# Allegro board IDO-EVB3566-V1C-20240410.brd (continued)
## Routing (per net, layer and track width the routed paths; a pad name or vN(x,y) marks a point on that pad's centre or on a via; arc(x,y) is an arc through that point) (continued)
FE1.1_DM3: length 18.6
  TOP w0.114: U26.12 83.81,15.5 83.94,15.37 83.94,15.12 85.27,13.79 88.35,13.79 89.08,14.52 89.08,15.93 89.28,16.13 90.28,16.13 90.81,16.66 90.81,19.66 91.36,20.22 91.36,22.73 90.81,23.29 90.81,23.82 90.93,23.95 91.26,23.95 91.37,23.83 91.37,23.7 R151.1
FE1.1_DM3_: length 6.5
  TOP w0.114: R151.2 92.74,24.02 D32.10 D32.1 94.91,24.02 95.04,24.15 95.4,24.15 95.89,24.64 95.89,25.19 96.54,25.84 96.66,25.84 96.77,25.72 J37.2
FE1.1_DM4: length 13.6
  TOP w0.114: U26.15 86.36,16.79 86.49,16.92 86.75,16.92 86.96,17.13 88.88,17.13 90.04,18.29 90.04,19.91 90.42,20.29 90.42,22.61 90.04,22.99 90.04,24 90.68,24.64 90.68,25.47 90.93,25.72 91.26,25.72 91.37,25.61 91.37,25.48 R156.1
FE1.1_DM4_: length 22.7
  TOP w0.114: R156.2 92.5,25.55 93.26,25.55 D32.7 D32.4 94.61,25.52 94.74,25.65 95.12,25.65 95.76,26.29 95.76,27.09 96.37,27.7 97.69,27.7 98.18,27.21 98.18,24.16 99.71,22.63 99.71,16.66 101.2,15.17 102.12,15.17 102.23,15.06 J38.2
FE1.1_DP1: length 25.6
  TOP w0.114: R132.1 91.12,27.74 90.92,27.74 90.59,27.4 90.59,26.59 89.83,25.83 89.83,25.35 88.41,23.93 79.25,23.93 78.71,23.39 78.02,23.39 76.73,22.11 76.73,18.79 77.36,18.16 80.09,18.16 80.21,18.29 U26.4
FE1.1_DP1_: length 15.9
  TOP w0.114: J13.3 102.23,26.14 102.12,26.03 100.71,26.03 99.44,27.3 99.44,29.84 98.81,30.48 96.65,30.48 95.68,29.51 95.68,28.48 95.14,27.95 94.76,27.95 94.65,28.05 D31.2 D31.9 93.08,27.84 92.58,27.84 R132.2
FE1.1_DP2: length 29.6
  TOP w0.114: R149.1 91.06,29.58 90.66,29.58 90.48,29.41 90.48,28.34 90.37,28.23 90.36,28.23 89.88,27.74 89.88,26.95 89.17,26.24 89.17,25.65 88.05,24.53 78.88,24.53 78.46,24.11 77.82,24.11 76.16,22.45 76.16,17.72 77.03,16.85 80.07,16.85 80.14,16.79 U26.7
FE1.1_DP2_: length 12.1
  TOP w0.114: J36.3 96.77,36.89 96.66,36.77 96.08,36.77 95.52,36.21 95.52,30.65 95.04,30.17 95.04,29.56 94.92,29.45 94.76,29.45 94.66,29.55 D31.5 D31.6 93.19,29.45 92.87,29.45 R149.2
FE1.1_DP3: length 18.6
  TOP w0.114: U26.13 84.31,15.48 84.18,15.35 84.18,15.22 84.5,14.91 84.66,14.91 84.73,14.98 84.89,14.98 85.05,14.82 85.05,14.66 84.98,14.58 84.98,14.42 85.37,14.03 88.25,14.03 88.84,14.62 88.84,16.03 89.18,16.37 90.18,16.37 90.56,16.76 90.56,19.76 91.12,20.32 91.12,22.63 90.56,23.19 90.56,23.92 90.83,24.19 91.26,24.19 91.37,24.3 91.37,24.43 R154.1
FE1.1_DP3_: length 6.5
  TOP w0.114: J37.3 96.77,26.19 96.66,26.08 96.44,26.08 95.64,25.29 95.64,24.74 95.3,24.39 95.04,24.39 94.91,24.52 D32.2 D32.9 93.07,24.3 92.87,24.3 92.83,24.26 92.6,24.26 R154.2
FE1.1_DP4: length 13.6
  TOP w0.114: U26.16 86.36,17.29 86.49,17.16 86.65,17.16 86.86,17.37 88.78,17.37 89.8,18.39 89.8,20.01 90.18,20.39 90.18,22.51 89.8,22.89 89.8,24.1 90.44,24.74 90.44,25.57 90.83,25.97 91.26,25.97 91.37,26.08 91.37,26.21 R159.1
FE1.1_DP4_: length 22.7
  TOP w0.114: J38.3 102.23,15.53 102.12,15.41 101.3,15.41 99.95,16.76 99.95,22.73 98.42,24.26 98.42,27.3 97.79,27.94 96.27,27.94 95.52,27.19 95.52,26.39 95.02,25.89 94.76,25.89 94.63,26.02 D32.5 D32.6 93.2,25.93 92.7,25.93 R159.2
FE1_1_DM0: length 2
  TOP w0.114: R299.2 79.31,19.81 79.63,19.49 79.8,19.49 79.97,19.66 80.13,19.66 80.26,19.79 U26.1
FE1_1_XIN: length 6.1
  TOP w0.127: U26.10 82.81,13.65 C203.2 82.91,12.87 82.91,11.45 XT5.1
FE1_1_XOUT: length 4.6
  TOP w0.127: U26.11 83.31,13.86 83.52,13.65 C202.2 83.26,13.05 83.26,12.5 83.56,12.2 XT5.3
FE2_1_DP0: length 2
  TOP w0.114: R298.2 79.31,18.92 79.63,19.25 79.9,19.25 80.07,19.42 80.13,19.42 80.26,19.29 U26.2
GMAC1_MCLKINOUT_M0: length 8.1
  TOP w0.127: v1(24.77,20.06) M1.79
  BOTTOM w0.127: v1(24.77,20.06) 25.28,20.06 27.76,17.58 C383.2 R1224.1
GMAC1_MDC_M0: length 12.6
  TOP w0.127: v1(24.64,22.61) 24.09,22.06 M1.77
  BOTTOM w0.127: v1(24.64,22.61) 25.02,22.99 25.8,22.99 25.92,22.88 25.92,22.21 26.03,22.1 26.19,22.1 26.3,22.21 26.3,22.88 26.41,22.99 26.57,22.99 26.68,22.88 26.68,21.96 26.79,21.84 26.95,21.84 27.06,21.96 27.06,22.88 27.17,22.99 27.53,22.99 28.14,23.6 30.89,23.6 31.13,23.36 U11.22
GMAC1_MDIO_M0: length 12.3
  TOP w0.127: v1(24.77,23.75) 24.08,23.06 M1.76
  BOTTOM w0.127: U11.23 31.26,23.86 31.12,24 29.62,24 R1204.2 29.03,24.59 27.76,24.59 26.92,23.75 26.76,23.75 26.65,23.86 26.65,24.53 26.54,24.64 26.38,24.64 26.27,24.53 26.27,23.86 26.16,23.75 26,23.75 25.89,23.86 25.89,24.53 25.78,24.64 25.62,24.64 25.51,24.53 25.51,23.86 25.39,23.75 v1(24.77,23.75)
GMAC1_RSTN: length 9.4
  TOP w0.127: v1(25.25,21.69) 25.25,19.28 24.64,18.67 24.64,17.27 24.43,17.06 M1.82
  BOTTOM w0.127: R1201.1 26.09,21.34 25.73,21.69 v1(25.25,21.69)
GMAC1_RXD0_M0: length 24.3
  TOP w0.127: v1(34.84,16.34) 34.39,15.89 34.23,15.89 33.49,16.63 33.49,16.79 33.86,17.16 33.86,17.32 33.75,17.43 33.59,17.43 33.22,17.06 33.06,17.06 32.85,17.27 32.69,17.27 32.58,17.16 32.58,17.01 32.8,16.78 32.8,16.63 32.68,16.5 32.68,16.35 32.79,16.23 32.95,16.23 33.07,16.36 33.23,16.36 33.96,15.62 33.96,15.47 33.66,15.16 33.66,14.91 33.77,14.79 34.28,14.79 34.39,14.68 34.39,14.52 34.28,14.41 33.72,14.41 33.6,14.3 33.6,14.14 33.72,14.03 34.28,14.03 34.39,13.92 34.39,13.76 34.28,13.65 34.01,13.65 33.89,13.54 33.89,12.94 33.78,12.83 33.63,12.83 33.51,12.94 33.51,13.54 33.4,13.65 33.15,13.65 33.02,13.52 33.02,12.93 32.89,12.81 32.71,12.81 32.6,12.92 32.6,13.48 32.49,13.59 32.33,13.59 32.22,13.48 32.22,12.92 32.11,12.81 31.95,12.81 31.84,12.92 31.84,13.48 31.73,13.59 31.57,13.59 31.46,13.48 31.46,12.92 31.09,12.55 30.71,12.55 30.03,11.87 M1.92
  BOTTOM w0.127: R1206.2 37.85,17.4 36.96,16.51 35.01,16.51 v1(34.84,16.34)
GMAC1_RXD1_M0: length 23.1
  TOP w0.127: M1.93 31.03,11.98 31.6,12.55 38.21,12.55 38.35,12.7 38.35,13.08 38.23,13.21 37.39,13.21 37.26,13.34 37.26,14.96 37.14,15.09 36.96,15.09 36.83,14.96 36.83,13.21 36.7,13.08 36.51,13.08 36.4,13.19 36.4,13.48 36.29,13.59 36.13,13.59 36.02,13.48 36.02,13.19 35.91,13.08 35.66,13.08 35.54,13.19 35.54,13.56 35.43,13.67 35.28,13.67 35.16,13.56 35.16,13.19 35.05,13.08 34.8,13.08 34.64,13.24 34.64,15.49 35.56,16.41 36.01,16.41 v1(36.58,16.98)
  BOTTOM w0.127: v1(36.58,16.98) 36.58,17.1 36.96,17.48 R1205.2
GMAC1_RXDV_CRS_M0: length 25.7
  TOP w0.127: v1(30.56,27.11) 30.77,27.11 31.28,26.59 31.28,26.13 30.23,25.08 30.23,19.46 30.86,18.82 30.86,16.13 30.78,16.05 30.78,15.45 31.06,15.16 31.06,13.9 30.25,13.08 28.7,13.08 28.43,12.81 26.9,12.81 26.03,11.94 M1.88
  BOTTOM w0.127: v1(30.56,27.11) R1209.2 29.97,26.77 30.35,26.39 30.35,26.19 30.93,25.61 32.7,25.61 33.04,25.27 U11.26
GMAC1_RXER_M0: length 24.9
  TOP w0.127: M1.87 25.03,12.08 25.65,12.7 26.44,12.7 26.8,13.06 28.17,13.06 28.45,13.34 30.14,13.34 30.73,13.93 30.73,15.13 30.52,15.34 30.52,16.15 30.61,16.23 30.61,18.72 29.97,19.35 29.97,25.48 30.82,26.33 v1(30.82,26.4)
  BOTTOM w0.127: U11.28 34.04,25.27 33.76,25.55 33.12,25.55 32.8,25.87 32.48,25.87 R1212.1 31.21,27.11 30.82,26.71 v1(30.82,26.4)
GMAC1_TXD0_M0: length 14.5
  TOP w0.127: M1.86 24.11,13.06 24.94,13.89 24.94,15.93 25.45,16.43 25.45,18.36 25.78,18.69 27.39,18.69 27.67,18.41 27.8,18.41 v1(27.82,18.39)
  BOTTOM w0.127: v1(27.82,18.39) 27.82,18.42 29,19.6 30.45,19.6 31.05,20.21 U11.16
GMAC1_TXD1_M0: length 13.2
  TOP w0.127: M1.85 24.09,14.06 24.61,14.58 24.61,16.21 25.1,16.69 25.1,18.47 25.69,19.06 v1(27.68,19.06)
  BOTTOM w0.127: U11.17 31.34,20.85 30.34,19.85 28.63,19.85 27.82,19.05 27.69,19.05 27.69,19.06 v1(27.68,19.06)
GMAC1_TXEN_M0: length 12.6
  TOP w0.127: M1.78 v1(24.77,21.06)
  BOTTOM w0.127: U11.20 31.37,22.36 29.84,20.83 27.36,20.83 27.25,20.72 27.25,19.92 27.14,19.81 26.98,19.81 26.87,19.92 26.87,20.72 26.76,20.83 26.6,20.83 26.49,20.72 26.49,19.92 26.38,19.81 26.22,19.81 26.11,19.92 26.11,20.72 25.99,20.83 25,20.83 v1(24.77,21.06)
GPIO0_A5_USB_OTG_PWREN: length 61.5
  TOP w0.127: U13.4 75.39,55.07 74.8,54.48 v1(71.85,54.48) ; v1(69.98,25.37) 70.48,24.87 M1.215 ; v1(66.77,50.27) 65.79,49.29 65.79,46.43 65.77,46.41 65.77,45.5 65.79,45.49 65.79,37.08 63.63,34.92 62.61,34.92 v1(61.85,34.16)
  BOTTOM w0.127: v1(61.85,34.16) 62.1,34.41 68.74,34.41 69.72,33.43 69.72,31.52 69.98,31.26 v1(69.98,25.37) ; v1(66.77,50.27) 67.08,49.95 67.62,49.95 68.07,50.4 68.07,51.82 70.23,53.98 71.34,53.98 v1(71.85,54.48) 73.15,55.78 74.24,55.78 74.58,56.12 74.58,56.68 74.89,56.98 74.89,59.07 74.02,59.94 R117.2
GPIO0_A6_USB_OTG0_DET: length 48.7
  TOP w0.127: v1(66.1,50.36) 65.53,49.8 65.53,46.53 65.52,46.52 65.52,45.4 65.53,45.38 65.53,37.19 63.65,35.31 62.23,35.31 v1(61.85,34.92) ; v1(65.28,55.3) 65,55.02 60.54,55.02 v1(60.38,55.18) ; M1.216 70.48,26.11 71.2,25.4 v1(71.53,25.4)
  BOTTOM w0.127: R120.1 v1(60.38,55.18) ; v1(61.85,34.92) 62.04,34.73 68.78,34.73 69.98,33.54 69.98,31.62 71.53,30.07 v1(71.53,25.4) ; v1(66.1,50.36) 66.1,54.81 65.61,55.3 v1(65.28,55.3)
GPIO0_B0_U_TP_INT_L: length 38
  TOP w0.127: v1(68.73,13.27) 66.13,13.27 65.89,13.51 65.89,13.69 65.56,14.02 65.56,14.32 65.51,14.37 65.51,14.55 65.45,14.61 65.45,15.16 65.51,15.22 65.51,15.36 64.47,16.39 64.47,17.63 64.16,17.95 64.16,34.44 67.69,37.97 71.41,37.97 72.5,39.06 M1.161
  BOTTOM w0.127: v1(68.73,13.27) 68.07,12.62 R44.1
GPIO0_C7_D_TP_RST_L: length 28.8
  TOP w0.127: M1.154 73.03,32.06 71.58,30.61 69.62,30.61 69.37,30.35 69.37,29.37 68.42,28.42 66.27,28.42 65.53,27.68 65.53,18.37 65.74,18.16 65.74,17.58 66.28,17.04 66.28,16.68 66.79,16.18 67.72,16.18 68.6,15.3 68.6,14.74 68.61,14.73 68.61,14.26 v1(68.66,14.2)
  BOTTOM w0.127: v1(68.66,14.2) 68.67,14.2 69.34,13.53 69.34,12.78 69.09,12.53 R43.1
GPIO0_D3_CIF_PDN_L: length 43.1
  TOP w0.127: M1.217 69.97,29.61 68.52,28.16 66.38,28.16 65.79,27.57 65.79,18.48 66,18.27 66,17.69 66.54,17.15 66.54,16.79 66.89,16.43 67.61,16.43 67.82,16.43 68.85,15.4 68.85,14.84 69.27,14.42 v1(69.3,14.42)
  BOTTOM w0.127: v1(69.3,14.42) 69.6,14.13 69.6,10.16 68.83,9.4 68.83,7.49 68.07,6.73 65.41,6.73 64.5,5.83 55.38,5.83 55.17,6.04 J10.6
GPIO2_B1_WIFI_REG_ON_H: length 72.7
  TOP w0.127: v1(30.95,40.11) 30.95,40.11 30.61,40.45 28.39,40.45 27.61,41.22 25.72,41.22 25.54,41.41 25.54,43.61 25.03,44.12 25.03,45.29 24.77,45.56 24.77,46.35 24.06,47.06 M1.52 ; v1(79.63,47.41) 79.63,46.23 80.34,45.52 U10.12
  BOTTOM w0.127: v1(79.63,47.41) 77.91,47.41 77.71,47.21 73.63,47.21 73.49,47.35 71.73,47.35 69.69,49.39 46.46,49.39 45.54,48.47 42.55,48.47 42.03,47.96 39.45,47.96 38.98,47.48 38.98,47.1 38.19,46.3 37.34,46.3 36.26,47.38 33.79,47.38 30.95,44.54 v1(30.95,40.11)
GPIO2_B2_WIFI_WAKE_HOST_H: length 74.7
  TOP w0.127: U10.13 80.22,44.62 78.99,45.85 v1(78.99,46.76) ; v1(30.93,39.06) 30.93,38.8 29.97,37.85 29.17,37.85 28.35,38.67 28.35,40.13 27.58,40.89 25.69,40.89 25.29,41.3 25.29,43.5 24.78,44.01 24.78,45.19 23.9,46.06 M1.53
  BOTTOM w0.127: v1(78.99,46.76) 78.62,46.39 78.32,46.39 78.29,46.35 78.11,46.35 78.08,46.32 73.26,46.32 73.2,46.39 70.99,46.39 68.91,48.46 45.89,48.46 45.64,48.22 42.65,48.22 42.14,47.7 39.73,47.7 39.24,47.21 39.24,46.99 38.29,46.05 37.23,46.05 36.15,47.13 33.9,47.13 31.42,44.65 31.42,39.55 v1(30.93,39.06)
GPIO2_B7_BT_REG_ON_H: length 57.1
  TOP w0.127: U10.34 v1(93.22,36.52) ; M1.225 42.89,45.51 v1(42.93,45.55)
  BOTTOM w0.127: v1(93.22,36.52) 87.62,36.52 79.54,44.61 79.06,44.61 78.05,43.6 70.23,43.6 69.97,43.87 69.76,43.87 69.64,43.99 68.15,43.99 67.99,44.15 58.85,44.15 58.5,44.5 51,44.5 50.03,45.47 43,45.47 v1(42.93,45.55)
GPIO2_C0_BT_WAKE_HOST_H: length 47
  TOP w0.127: M1.182 42.26,47.84 42.78,47.84 v1(42.86,47.75) ; v1(85.09,47.88) 85.71,47.25 U10.7
  BOTTOM w0.127: v1(85.09,47.88) 82.69,47.88 80.95,46.13 78.43,46.13 78.39,46.1 78.22,46.1 78.18,46.07 73.16,46.07 73.09,46.13 70.88,46.13 68.88,48.13 68.46,48.13 68.46,48.13 45.92,48.13 45.75,47.96 43.23,47.96 43.02,47.75 v1(42.86,47.75)
GPIO2_C1_HOST_WAKE_BT_H: length 52.5
  TOP w0.127: M1.226 38.58,46.58 39.23,47.24 v1(39.92,47.24) ; U10.6 86.61,47.52 86.25,47.88 v1(85.77,47.88)
  BOTTOM w0.127: v1(39.92,47.24) 39.97,47.29 43.75,47.29 44.04,47 45.35,47 46.23,47.88 68.56,47.88 68.77,47.88 70.77,45.88 72.99,45.88 73.05,45.81 78.29,45.81 78.32,45.85 78.5,45.85 78.53,45.88 80.57,45.88 81.05,45.88 82.54,47.37 85.26,47.37 v1(85.77,47.88)
GPIO2_C6_CIF_RST_L: length 126.2
  TOP w0.127: v1(54.67,7.7) 51.36,7.7 51.18,7.87 51.18,8.76 50.88,9.07 48.18,9.07 47.57,8.46 v1(45.49,8.46) ; v1(3.96,14.1) 3.96,12.06 9.93,6.1 12.32,6.1 v1(12.83,5.59) ; v1(3.96,18.87) 3.96,20.02 3.66,20.32 3.66,37.47 3.84,37.64 3.84,39.25 4.75,40.16 4.75,49.83 5.59,50.67 8.2,50.67 11.38,53.85 19.3,53.85 20.7,52.45 29.91,52.45 30.03,52.32 M1.43
  BOTTOM w0.127: v1(54.67,7.7) J10.5 ; v1(3.96,14.1) v1(3.96,18.87) ; v1(12.83,5.59) 13.31,6.07 16.79,6.07 17.27,5.59 23.62,5.59 24.13,6.1 31.24,6.1 31.54,5.8 36.93,5.8 37.34,6.21 40.34,6.21 44.06,9.93 45.16,9.93 45.29,9.8 45.29,8.66 v1(45.49,8.46)
GPIO3_D6_SPK_CTRL_L: length 77
  TOP w0.127: U25.1 81.62,27.77 82.08,28.23 82.08,30.95 81.95,31.07 U24.1 80.27,31.07 ; M1.75 24.06,24.06 25,25 25,27.28 25.23,27.52 25.23,30.31 24.78,30.77 24.78,32.63 v1(25.02,32.87) ; 80.27,31.07 80.25,31.07 79.32,32 77.82,32 77.29,31.48 v1(77.29,31.26) ; 80.27,31.07 R199.2
  BOTTOM w0.127: v1(25.02,32.87) 25.19,33.04 29.82,33.04 30.07,33.29 31.23,33.29 33.99,36.06 45.78,36.06 46.51,36.78 52.09,36.78 53.45,35.43 59.69,35.43 61.3,37.04 63.78,37.04 64.13,36.69 69.76,36.69 73.05,33.4 73.13,33.4 75.17,31.36 77.19,31.36 v1(77.29,31.26)
GPIO3_D7_LVDS_ON: length 83.8
  TOP w0.127: J7.36 74.55,10.23 75.18,10.87 v1(75.18,12.32) ; M1.74 23.2,25.06 22.81,24.67 22.81,23.06 22.27,22.52 22.27,10.66 22.86,10.07 22.86,7.74 v1(22.81,7.69)
  BOTTOM w0.127: v1(75.18,12.32) 75.18,12.38 74.76,12.81 74.76,13.32 72.61,15.47 71.95,15.47 71.27,16.15 71.27,16.55 70.68,17.14 65.09,17.14 64.41,16.47 63.6,16.47 63.18,16.89 50.72,16.89 48.79,14.96 46.63,14.96 46.06,14.39 45.54,14.39 39.68,8.53 36.55,8.53 35.88,7.85 32.98,7.85 32.58,8.26 28.38,8.26 27.98,7.85 22.97,7.85 v1(22.81,7.69)
GPIO4_A0_MIPI_TX1_RST_L: length 32.8
  TOP w0.127: v1(33.02,9.02) 33.02,8.31 R342.1 ; M1.72 22.84,26.37 22.84,25.6 22.56,25.31 22.56,23.17 22.01,22.63 22.01,8.42 v1(21.78,8.19)
  BOTTOM w0.127: v1(33.02,9.02) 32.74,9.3 28.71,9.3 27.77,8.36 23.15,8.36 22.85,8.65 22.24,8.65 v1(21.78,8.19)
GPIO4_B0_USB_HOST1_PWREN_H: length 77.4
  TOP w0.127: v1(59.45,35.9) 59.69,36.13 59.69,50.35 v1(59.54,50.51) ; v1(30.4,34.01) 30.62,34.22 30.62,34.97 27.56,38.02 25.47,38.02 24.78,38.72 24.78,40.37 24.09,41.06 M1.58
  BOTTOM w0.127: v1(59.54,50.51) 60.56,50.51 60.73,50.67 62.12,50.67 63.88,52.43 63.88,54.61 64.35,55.08 64.35,58.71 60.71,62.36 59.56,62.36 58.87,63.05 U14.4 ; v1(59.45,35.9) 59.24,35.69 53.55,35.69 52.2,37.04 50,37.04 49.32,37.72 44.32,37.72 43.17,36.56 33.75,36.56 31.2,34.01 v1(30.4,34.01)
GPIO4_B1_CIF_PWREN_H: length 93.3
  TOP w0.127: v1(21.12,8) 21.12,8.7 21.76,9.34 21.76,22.73 22.3,23.27 22.3,25.41 22.59,25.7 22.59,26.48 22.84,26.73 22.84,28.93 22.97,29.06 M1.70
  BOTTOM w0.127: R1221.1 77.12,8.23 77.37,8.23 77.85,8.71 77.85,9.96 78.74,10.85 78.74,12.31 77.71,13.34 75.11,13.34 72.72,15.72 72.05,15.72 71.52,16.25 71.52,16.66 70.78,17.4 64.98,17.4 64.31,16.72 63.71,16.72 63.29,17.14 50.62,17.14 48.68,15.21 46.52,15.21 45.95,14.64 45.44,14.64 39.58,8.78 36.45,8.78 35.77,8.1 33.09,8.1 32.43,8.76 28.53,8.76 27.87,8.1 23.05,8.1 23,8.15 22.42,8.15 21.99,7.72 21.4,7.72 v1(21.12,8)
GPIO4_B4_USB_FE_D4_PWREN_H: length 100.7
  TOP w0.127: M1.68 23.06,31.06 22.59,30.59 22.59,26.84 22.33,26.58 22.33,25.81 22.05,25.52 22.05,23.38 21.51,22.84 21.51,9.44 20.45,8.38 v1(20.45,7.95)
  BOTTOM w0.127: U19.4 86.8,12.13 86.49,12.45 86.49,13.54 85.33,14.7 78.87,14.7 75.91,17.65 64.88,17.65 64.2,16.98 63.82,16.98 63.39,17.4 50.51,17.4 48.61,15.49 46.45,15.49 45.85,14.89 45.33,14.89 39.47,9.03 34.87,9.03 34.35,9.55 28.6,9.55 27.66,8.61 23.25,8.61 22.96,8.91 21.09,8.91 20.45,8.26 v1(20.45,7.95)
GPIO4_B5_HUB_XRSTJ: length 96.5
  TOP w0.127: v1(89.53,20.57) 89.53,18.82 88.62,17.91 R343.2 ; M1.67 24.06,32.06 24.52,32.52 24.52,33.03 25.65,34.16 27.49,34.16 27.57,34.08 28.28,34.08 28.49,33.87 28.49,29.88 v1(28.28,29.67) ; v1(48.51,33.99) 47.96,33.44 47.96,32.01 47.75,31.8 47.75,25.71 47.94,25.52 47.94,24.92 47.65,24.64 47.65,23.46 46.84,22.65 46.84,22.64 46.84,22.63 46.74,22.53 46.74,21.37 v1(46.96,21.15)
  BOTTOM w0.127: v1(89.53,20.57) 89.51,20.6 88.32,20.6 87.51,21.41 86.14,21.41 84.69,22.85 80.29,22.85 79.75,23.39 76.1,23.39 72.39,19.68 69.58,19.68 69.08,19.19 67.98,19.19 67.51,19.66 64.57,19.66 64.1,19.19 48.94,19.19 47.09,21.03 47.07,21.03 v1(46.96,21.15) ; v1(28.28,29.67) 28.33,29.72 30.48,29.72 30.73,29.97 31.78,29.97 31.78,29.97 31.9,29.97 35.24,33.31 47.84,33.31 v1(48.51,33.99)
GPIO4_B6_USB_FE_D2_PWREN_H: length 75.8
  TOP w0.127: v1(30.06,34.59) 30.06,34.6 30.06,35.16 27.45,37.77 25.37,37.77 24.52,38.62 24.52,39.61 24.07,40.06 M1.59
  BOTTOM w0.127: U17.4 88.84,30.8 89.28,31.24 89.28,32.98 89.07,33.19 86.76,33.19 85.95,32.38 82.47,32.38 81.2,33.66 73.15,33.66 69.87,36.94 64.28,36.94 63.93,37.29 50.11,37.29 49.43,37.97 44.2,37.97 43.04,36.82 33.64,36.82 31.42,34.59 v1(30.06,34.59)
GPIO4_B7_USB_FE_D3_PWREN_H: length 91.8
  TOP w0.127: M1.64 24.65,35.06 24.89,35.31 27.43,35.31 27.89,34.84 28.7,34.84 29.25,34.29 29.25,29.91 v1(29.97,29.19) ; v1(49.19,34.07) 49.15,34.03 49.15,33.96 48.71,33.52 48.63,33.52 48.22,33.1 48.22,31.91 48.01,31.7 48.01,25.81 48.19,25.63 48.19,24.82 47.9,24.53 47.9,23.34 47.38,22.82 47.37,22.82 47.09,22.55 47.09,22.53 47.09,22.53 47.09,21.89 v1(47.21,21.77)
  BOTTOM w0.127: U18.4 87.82,22.04 87.53,21.74 86.23,21.74 84.87,23.11 80.45,23.11 79.91,23.65 75.97,23.65 72.26,19.94 69.47,19.94 69.45,19.91 68.97,19.44 68.09,19.44 67.61,19.91 64.47,19.91 63.99,19.44 49.22,19.44 47.42,21.23 47.42,21.34 47.21,21.55 v1(47.21,21.77) ; v1(49.19,34.07) 49.15,34.03 49.15,33.96 48.71,33.52 48.68,33.52 48.22,33.06 35.36,33.06 32.02,29.72 31.89,29.72 31.89,29.72 30.87,29.72 30.35,29.19 v1(29.97,29.19)
GPIO4_C0_USB_HOST2_PWREN_H: length 96.9
  TOP w0.127: v1(47.56,22.36) 47.56,22.44 48.16,23.04 48.16,24.43 48.45,24.71 48.45,25.73 48.26,25.92 48.26,31.59 48.47,31.8 48.47,32.94 48.79,33.27 48.81,33.27 49.1,33.55 49.35,33.55 49.74,33.94 49.74,36.64 49.13,37.25 v1(49.03,37.25) ; v1(29.72,33.6) 29.59,33.73 29.59,35.27 27.35,37.52 25.26,37.52 25.24,37.54 23.72,39.06 M1.60
  BOTTOM w0.127: v1(29.72,33.6) 29.9,33.6 29.95,33.55 31.12,33.55 33.88,36.31 45.68,36.31 46.7,37.34 48.94,37.34 v1(49.03,37.25) ; v1(47.56,22.36) 47.56,22.35 47.56,22.08 47.68,21.97 47.68,21.48 49.46,19.69 63.89,19.69 64.36,20.17 67.72,20.17 68.19,19.69 68.87,19.69 69.37,20.19 72.16,20.19 75.87,23.9 80.11,23.9 80.65,23.36 85.12,23.36 86.39,22.1 87,22.1 87.96,23.06 89.15,23.06 89.25,23.16 89.25,25.76 88.9,26.1 U27.4
GPIO4_C1_USB_FE_D1_PWREN_H: length 95.9
  TOP w0.127: v1(47.5,32.21) 47.5,25.6 47.68,25.42 47.68,25.03 47.4,24.74 47.4,23.57 46.43,22.61 46.43,20.93 v1(46.89,20.47) ; v1(28.07,28.69) 28.74,29.36 28.74,34.08 28.49,34.33 27.68,34.33 27.47,34.54 25.53,34.54 24.05,33.06 M1.66
  BOTTOM w0.127: v1(46.89,20.47) 48.43,18.93 64.2,18.93 64.68,19.4 67.34,19.4 67.81,18.93 69.18,18.93 69.68,19.43 72.64,19.43 76.35,23.14 79.6,23.14 80.19,22.56 84.53,22.56 86,21.08 87.4,21.08 88.21,20.27 89.14,20.27 89.36,20.05 89.36,17.41 89.03,17.08 U15.4 ; v1(47.5,32.21) 47.15,32.55 35.57,32.55 32.23,29.21 32.1,29.21 32.1,29.21 31.08,29.21 30.35,28.47 28.28,28.47 v1(28.07,28.69)
HDMI_TX_CEC_PORT: length 7.4
  TOP w0.127: Q1.3 84.22,53.98 84.07,54.12 84.07,54.48 84.48,54.89 D9.1 83.98,56.92 J6.13
HDMI_TX_CLKN: length 48.3
  TOP w0.102: M1.139 73.91,17.43 74.17,17.43 75.74,19.01 75.74,22.5 76.76,23.52 76.76,43.94 76.76,43.95 76.76,44.53 76.76,44.54 76.76,46.96 78.72,48.92 78.72,52.18 81.59,55.05 82.46,55.05 83.1,55.68 83.1,56.12 83.22,56.24 D7.5 D7.6 83.22,57.55 83.1,57.67 83.1,58.79 83.48,59.17 J6.12
HDMI_TX_CLKP: length 48.3
  TOP w0.102: J6.10 82.48,59.17 82.84,58.81 82.84,57.7 82.72,57.57 D7.7 D7.4 82.72,56.22 82.84,56.1 82.84,55.79 82.36,55.3 81.48,55.3 78.47,52.28 78.47,49.03 76.5,47.07 76.5,44.64 76.5,44.64 76.5,43.84 76.5,43.84 76.5,23.63 75.49,22.61 75.49,19.12 75.11,18.74 74.97,18.74 74.86,18.84 74.72,18.84 74.58,18.7 74.58,18.55 74.68,18.45 74.68,18.31 74.06,17.69 73.91,17.69 M1.140
HDMI_TX_D0N: length 47.8
  TOP w0.102: J6.9 81.98,59.17 81.6,58.79 81.6,57.72 81.72,57.6 D7.9 D7.2 81.72,56.22 81.57,56.07 81.57,55.88 81.32,55.63 81.03,55.63 77.98,52.58 77.98,48.9 77.57,48.48 77.21,48.48 76.56,49.13 76.42,49.13 76.13,48.85 76.13,48.7 76.78,48.05 76.78,47.7 76.1,47.02 76.1,23.7 75.13,22.73 75.13,19.75 74.81,19.44 73.92,19.44 73.54,19.06 M1.141
HDMI_TX_D0P: length 47.8
  TOP w0.102: J6.7 80.98,59.17 81.34,58.81 81.34,57.72 81.22,57.6 D7.10 D7.1 81.22,56.22 81.32,56.12 81.32,55.98 81.22,55.88 80.92,55.88 77.72,52.68 77.72,49 77.46,48.74 77.32,48.74 76.67,49.39 76.31,49.39 75.88,48.95 75.88,48.6 76.53,47.95 76.53,47.8 75.84,47.12 75.84,23.8 74.87,22.83 74.87,20.82 74.77,20.72 74.65,20.72 74.55,20.62 74.55,20.42 74.65,20.32 74.77,20.32 74.87,20.21 74.87,19.86 74.7,19.69 73.91,19.69 M1.142
HDMI_TX_D1N: length 46.3
  TOP w0.102: J6.6 80.48,59.17 80.1,58.8 80.1,57.7 80.22,57.57 D6.6 D6.5 80.22,56.22 80.1,56.1 80.1,55.84 77.22,52.96 77.22,52.07 76.97,51.82 75.54,51.82 75.44,51.71 75.44,51.28 75.54,51.18 76.83,51.18 77.09,50.93 77.09,50.29 76.84,50.04 75.49,50.04 75.39,49.94 75.39,23.8 74.46,22.88 74.46,21.76 74.14,21.44 73.91,21.44 M1.143
HDMI_TX_D1P: length 46.2
  TOP w0.102: M1.144 73.91,21.69 74.03,21.69 74.21,21.87 74.21,22.98 75.13,23.91 75.13,50.04 75.38,50.29 76.73,50.29 76.83,50.39 76.83,50.82 76.73,50.93 75.43,50.93 75.18,51.18 75.18,51.82 75.43,52.07 76.86,52.07 76.96,52.17 76.96,53.06 79.15,55.25 79.15,55.4 79.07,55.48 79.07,55.62 79.21,55.77 79.35,55.77 79.44,55.68 79.58,55.68 79.85,55.95 79.85,56.04 79.72,56.17 D6.4 D6.7 79.72,57.62 79.85,57.75 79.85,58.81 79.48,59.17 J6.4
HDMI_TX_D2N: length 47
  TOP w0.102: M1.145 73.91,23.44 74.24,23.44 74.73,23.93 74.73,52.38 74.16,52.94 72.76,52.94 72.66,53.05 72.66,53.51 72.76,53.61 74.59,53.61 75.38,52.82 75.73,52.82 76.17,53.25 76.17,53.61 75.68,54.09 75.68,54.24 75.97,54.53 76.11,54.53 76.6,54.04 76.95,54.04 78.6,55.69 78.6,56.12 78.72,56.24 D6.2 D6.9 78.72,57.55 78.6,57.67 78.6,58.87 78.98,59.25 J6.3
HDMI_TX_D2P: length 47
  TOP w0.102: J6.1 77.98,59.25 78.35,58.88 78.35,57.67 78.22,57.55 D6.10 D6.1 78.22,56.27 78.35,56.15 78.35,55.79 78.12,55.57 77.97,55.57 77.89,55.65 77.75,55.65 77.6,55.51 77.6,55.36 77.69,55.28 77.69,55.14 76.85,54.29 76.7,54.29 76.22,54.78 75.86,54.78 75.43,54.34 75.43,53.99 75.91,53.5 75.91,53.36 75.62,53.07 75.48,53.07 74.69,53.86 72.66,53.86 72.41,53.61 72.41,52.94 72.66,52.69 74.06,52.69 74.47,52.27 74.47,24.03 74.13,23.69 73.91,23.69 M1.146
HDMI_TX_HPD_PORT: length 7.4
  TOP w0.127: J6.19 86.98,58.91 v1(86.61,58.55)
  BOTTOM w0.127: R30.2 R28.2 87.12,56.26 87.33,56.47 87.33,57.34 87.02,57.66 86.33,57.66 D8.1 86.23,58.17 v1(86.61,58.55)
HDMI_TX_HPDIN: length 80.9
  TOP w0.127: M1.135 73.9,13.06 74.3,13.46 76.17,13.46 v1(76.51,13.8)
  BOTTOM w0.127: v1(76.51,13.8) 77.61,13.8 78.99,12.41 78.99,10.39 79.96,9.42 97.94,9.42 99.92,11.4 99.92,16.36 100.81,17.25 100.81,31.39 99.92,32.28 99.92,39.57 95.43,44.07 93.27,44.07 91.69,45.65 91.69,46.61 88.77,49.53 88.77,50.75 87.12,52.4 R28.1
HDMI_TXDDC_SCL_PORT: length 8.9
  TOP w0.127: J6.15 84.98,58.94 v1(84.58,58.55)
  BOTTOM w0.127: v1(84.58,58.55) 84.48,58.55 D10.1 84.23,57.22 84.23,55.57 84.07,55.42 R32.2 84.07,54.91 Q2.3
HDMI_TXDDC_SDA_PORT: length 9.6
  TOP w0.127: J6.16 v1(85.48,58.55)
  BOTTOM w0.127: v1(85.48,58.55) 85.48,58.25 D11.1 84.48,57.25 84.48,55.64 R34.2 85.34,54.78 85.34,52.96 85.47,52.83 86.2,52.83 Q3.3
HDMITX_CEC_M0: length 88.9
  TOP w0.127: M1.138 74.35,16.06 74.68,15.74 74.68,14.93 v1(74.79,14.82) ; R29.1 85.85,52.27 85.22,52.27 84.02,53.47 83.08,53.47 Q1.2 82.3,53.48 v1(82.3,53.47)
  BOTTOM w0.127: v1(82.3,53.47) 82.93,52.83 82.93,49.91 83.95,48.9 87.63,48.9 88.21,48.31 88.21,46.33 91.53,43.02 94.9,43.02 98.7,39.22 98.7,32.16 100.05,30.81 100.05,17.68 98.7,16.33 98.7,11.56 97.36,10.21 86.79,10.21 85.47,11.54 85.47,13.34 84.87,13.94 78.55,13.94 77.67,14.82 v1(74.79,14.82)
HDMITX_SCL: length 81.1
  TOP w0.127: v1(75.16,14.18) 74.59,14.18 73.71,15.06 M1.137
  BOTTOM w0.127: v1(75.16,14.18) 75.49,14.52 77.61,14.52 78.44,13.68 84.77,13.68 85.22,13.23 85.22,11.43 86.69,9.96 97.61,9.96 99.14,11.48 99.14,16.36 100.3,17.53 100.3,30.96 99.14,32.13 99.14,39.4 95.17,43.36 91.64,43.36 88.47,46.53 88.47,48.46 87.78,49.15 84.59,49.15 R31.2 83.57,50.17 Q2.2
HDMITX_SDA: length 79.1
  TOP w0.127: v1(75.82,13.93) 75.61,13.72 74.42,13.72 74.08,14.06 M1.136
  BOTTOM w0.127: Q3.2 85.99,50.17 R33.2 86.49,49.66 88.16,49.66 91.39,46.43 91.39,45.44 93.17,43.66 95.3,43.66 99.52,39.45 99.52,32.23 100.56,31.19 100.56,17.4 99.52,16.36 99.52,11.46 97.74,9.68 80.07,9.68 79.25,10.5 79.25,12.52 77.5,14.27 75.95,14.27 75.82,14.13 v1(75.82,13.93)
HP_DET_L: length 119.2
  TOP w0.127: v1(30.76,45.85) 30.82,45.78 30.82,44.24 31.24,43.81 31.84,43.81 35.31,40.35 35.31,37.39 31.96,34.04 31.96,25.1 30.48,23.62 30.48,19.56 31.11,18.93 31.11,16.02 31.03,15.94 31.03,15.56 31.42,15.17 31.42,13.89 30.35,12.83 28.96,12.83 28.68,12.55 27.41,12.55 27.03,12.17 M1.89
  BOTTOM w0.127: v1(30.76,45.85) 31.9,45.85 33.69,47.64 36.36,47.64 37.44,46.56 38.08,46.56 38.73,47.2 38.73,47.59 39.35,48.21 41.93,48.21 42.44,48.72 45.43,48.72 46.41,49.7 67.73,49.7 68.33,50.3 68.33,51.69 70.36,53.72 71.75,53.72 73.35,55.32 74.75,55.32 78.49,59.05 84.99,59.05 89.09,63.15 92.39,63.15 93.12,62.43 R166.1
HP_SNS: length 47.4
  TOP w0.203: M1.8 65.03,52.11 65.94,53.01 67.24,53.01 68.38,54.14 68.38,56.92 68.58,57.12 70.93,57.12 71.14,57.32 71.14,61.32 73.48,63.66 85.42,63.66 85.94,64.18 87.04,64.18 87.54,64.69 90.59,64.69 90.93,65.02 91.89,65.02 R165.2 93.01,66.14 97.36,66.14 98.44,67.23 J34.4
HPL_OUT: length 72.9
  TOP w0.203: C157.2 91.19,59.82 90.93,60.07 90.93,62.71 89.38,64.26 87.63,64.26 87.22,63.85 86.08,63.85 85.55,63.33 73.61,63.33 71.47,61.18 71.47,57.19 71.07,56.79 68.91,56.79 68.71,56.59 68.71,54.01 67.38,52.68 66.52,52.68 66.03,52.2 M1.7 66.03,51.17 64.77,49.91 63.71,49.91 63.12,49.32 63.12,37.04 v1(63.59,36.57) ; v1(77.29,30.54) 78.03,31.29 C187.1
  BOTTOM w0.203: v1(63.59,36.57) 63.77,36.39 69.57,36.39 75.16,30.81 77.02,30.81 v1(77.29,30.54)
HPL_OUT+: length 11.9
  TOP w0.203: C157.1 92.68,60.81 R331.1 92.68,60.86 D37.1 98.55,62.1 99.98,60.68 101.56,60.68 J34.2
HPR_OUT: length 74.9
  TOP w0.203: C195.1 77.14,28.29 77.14,29.64 v1(77.32,29.82) ; v1(90.51,64.14) 90.59,64.14 91.48,63.25 C160.2 ; v1(62.87,36.57) 62.74,36.7 62.74,49.4 64.03,50.7 M1.9 64.03,51.57 65.8,53.34 67.11,53.34 68.05,54.28 68.05,62.84 69.2,63.99 85.28,63.99 85.98,64.69 87.08,64.69 87.58,65.19 v1(88.14,65.19)
  BOTTOM w0.203: v1(77.32,29.82) 77.29,29.82 76.63,30.48 74.96,30.48 69.37,36.06 63.37,36.06 v1(62.87,36.57) ; v1(90.51,64.14) 89.15,64.14 88.14,65.15 v1(88.14,65.19)
HPR_OUT+: length 2.9
  TOP w0.203: C160.1 92.65,63.82 92.68,63.85 D39.1 92.77,64.48 J34.3
HUB_RSTJ: length 1.6
  TOP w0.127: U26.17 86.4,17.79 86.53,17.92 86.94,17.92 86.94,17.91 R343.1
I2C1_SCL_TP: length 33.2
  TOP w0.127: M1.160 72.73,38.06 72.31,37.64 67.72,37.64 64.44,34.36 64.44,18.03 64.73,17.74 64.73,16.5 65.81,15.41 65.81,15.16 65.7,15.05 65.7,14.71 65.81,14.6 65.81,14.43 66.03,14.21 v1(66.03,14.21)
  BOTTOM w0.127: R41.1 66.76,14.21 v1(66.03,14.21)
I2C1_SDA_TP: length 32.4
  TOP w0.127: v1(66.12,14.88) 66.12,15.47 64.98,16.6 64.98,17.84 64.72,18.11 64.72,34.28 65.19,34.75 71.04,34.75 72.09,35.79 72.09,36.22 72.93,37.06 M1.159
  BOTTOM w0.127: R39.1 65.41,14.17 65.41,14.73 65.56,14.88 v1(66.12,14.88)
I2C2_SCL_M0_RTC: length 13.9
  TOP w0.127: v1(67.35,22.32) 68.2,22.32 68.55,22.68 68.55,27.05 68.91,27.4 68.91,27.4 69.39,27.88 71.7,27.88 72.52,27.06 M1.149
  BOTTOM w0.127: v1(67.35,22.32) 67.83,22.8 R22.1 67.68,23.12 67.15,23.12 66.94,23.33 R23.2
I2C2_SDA_M0_RTC: length 8.5
  TOP w0.127: M1.147 72.64,25.06 72.26,24.68 72.26,23.41 v1(72.26,23.4)
  BOTTOM w0.127: v1(72.26,23.4) 72.09,23.4 71.44,22.75 71.44,22.27 70.93,21.76 70.37,21.76 69.32,22.8 R21.1 68.99,22.99 R24.2
I2C3_SCL_M0_OUT: length 30.7
  TOP w0.127: v1(14.22,12.56) 13.75,12.56 R194.1 13.54,13.51 13.32,13.73 D45.6 D45.5 10.56,13.73 9.9,13.07 8.27,13.07 J31.8 ; M1.200 32.58,15.71 v1(32.62,15.75)
  BOTTOM w0.127: v1(14.22,12.56) 14.84,12.56 15.61,13.33 15.61,13.5 16.15,14.04 27.49,14.04 27.7,13.83 28.08,13.83 28.32,14.07 29.69,14.07 29.95,14.33 32.59,14.33 32.62,14.35 v1(32.62,15.75)
I2C3_SDA_M0_OUT: length 32.5
  TOP w0.127: v1(15.08,13.51) 15.08,12.86 R193.1 14.81,12.77 13.35,14.23 D45.7 D45.4 10.55,14.23 9.68,13.37 8.8,13.37 8,14.17 8,14.61 7.14,15.46 J31.6 ; v1(27.89,14.3) 27.89,14.67 28.3,15.08 28.3,19.45 28.19,19.56 27.05,19.56 26.58,20.03 M1.196
  BOTTOM w0.127: v1(15.08,13.51) 15.08,13.61 15.77,14.3 v1(27.89,14.3)
I2C4_SCL_M0_MIPI CSI: length 61.6
  TOP w0.127: v1(31.07,6.62) 30.59,7.11 28.6,7.11 24.49,11.22 24.49,12.3 25.15,12.95 26.33,12.95 26.69,13.31 28.05,13.31 28.4,13.67 28.4,14.83 28.55,14.97 28.55,19.56 28.5,19.61 28.5,19.63 28.32,19.81 27.91,19.81 27.58,20.13 27.58,27.48 29,28.89 29,34.19 28.6,34.59 27.79,34.59 27.45,34.92 25.27,34.92 24.41,34.06 M1.65
  BOTTOM w0.127: R334.2 47.14,11.47 Q8.3 45.24,11.47 40.24,6.47 37.24,6.47 36.82,6.05 31.64,6.05 v1(31.07,6.62)
I2C4_SDA_M0_MIPI CSI: length 63.8
  TOP w0.127: v1(19.81,9.53) 20.23,9.53 21.24,10.54 21.24,22.93 21.79,23.48 21.79,25.62 22.08,25.91 22.08,26.69 22.33,26.94 22.33,30.69 22.69,31.05 22.69,35.22 M1.63 ; v1(26.8,9.65) 26.8,9.27 28.7,7.37 31.03,7.37 v1(31.75,6.65)
  BOTTOM w0.127: v1(26.8,9.65) 23.67,9.65 23.17,10.16 20.73,10.16 20.09,9.53 v1(19.81,9.53) ; v1(31.75,6.65) 32.09,6.31 36.71,6.31 37.13,6.72 40.13,6.72 46.11,12.7 46.66,12.7 R333.2 47.3,13.34 49.28,13.34 49.66,12.95 Q9.3
I2C_SCL_RTC: length 1.7
  BOTTOM w0.127: R23.1 67.84,23.75 67.84,23.75 U5.6
I2C_SDA_RTC: length 1.8
  BOTTOM w0.127: U5.5 68.49,24.41 68.76,24.13 R24.1
I2S2_LRCK_TX_M0_WIFI: length 72.2
  TOP w0.127: v1(85.72,33.3) 86.45,33.3 86.73,33.57 86.73,34.75 86.61,34.86 U10.28 ; v1(36.1,38.99) 35.86,39.22 35.86,40.15 31.95,44.06 31.52,44.06 31.39,44.19 31.39,46.46 31.12,46.73 31.12,49.42 30.25,50.29 28.7,50.29 28.03,50.96 M1.45
  BOTTOM w0.127: v1(85.72,33.3) 85.72,33.39 85.6,33.51 83.31,33.51 82.15,34.67 73.83,34.67 70.55,37.96 65,37.96 64.65,38.31 51.13,38.31 50.68,38.76 46.97,38.76 46.52,39.2 39.71,39.2 39.5,38.99 v1(36.1,38.99)
I2S2_SCLK_TX_M0_WIFI: length 66.6
  TOP w0.127: v1(85.12,34.26) 84.81,34.57 U10.26 ; M1.42 31.03,50.88 32,49.91 33.78,49.91 34.04,49.66 34.04,44.68 34.42,44.3 34.98,44.3 37.83,41.45 38.48,41.45 38.65,41.29 v1(38.65,40.76)
  BOTTOM w0.127: v1(38.65,40.76) 38.7,40.76 38.82,40.64 42.29,40.64 42.67,41.02 47.71,41.02 48.96,39.77 54.83,39.77 55.2,39.4 66.74,39.4 67.16,38.97 71.26,38.97 74.55,35.69 84.07,35.69 85.12,34.64 v1(85.12,34.26)
I2S2_SDI_M0_WIFI: length 66.1
  TOP w0.127: M1.41 32.03,51.15 32.87,50.32 33.93,50.32 34.29,49.95 34.29,44.83 34.56,44.56 35.09,44.56 37.94,41.71 v1(38.89,41.71) ; U10.25 83.91,34.97 83.66,34.71 v1(83.66,34.37)
  BOTTOM w0.127: v1(38.89,41.71) 38.84,41.76 38.56,41.76 37.85,41.04 37.85,40.13 38.23,39.75 39.12,39.75 39.37,40.01 43.81,40.01 44.07,40.26 47.76,40.26 48.75,39.26 50.89,39.26 51.34,38.82 65.05,38.82 65.4,38.46 70.76,38.46 74.04,35.18 82.85,35.18 v1(83.66,34.37)
I2S2_SDO_M0_WIFI: length 69.8
  TOP w0.127: M1.44 29.03,51 29.46,50.57 30.33,50.57 31.37,49.53 31.37,46.84 31.64,46.57 31.64,44.44 31.77,44.32 32.05,44.32 36.23,40.14 36.23,39.92 v1(36.69,39.45) ; v1(86.25,33.77) 86.26,33.77 86.26,34.5 85.71,35.05 U10.27
  BOTTOM w0.127: v1(36.69,39.45) 36.91,39.24 39.39,39.24 39.6,39.46 46.63,39.46 47.07,39.01 50.79,39.01 51.23,38.56 64.94,38.56 65.29,38.21 70.65,38.21 73.94,34.92 82.25,34.92 83.41,33.77 v1(86.25,33.77)
LCD_SELF_TEST: length 2.6
  TOP w0.127: v1(19.56,5.08) 19.57,5.09 J5.17
  BOTTOM w0.127: v1(19.56,5.08) 20.07,4.57 TP1.1
LED0/PHYAD0: length 46.6
  TOP w0.127: v1(34.8,43.81) 34.67,43.94 34.42,43.94 33.78,44.58 33.78,46.48 33.02,47.24 v1(32.38,47.24) ; v1(34.11,53.09) 31.7,53.09 29.03,55.75 J12.10 ; v1(31.89,40.07) 32.26,40.07 32.68,39.65 32.68,36.47 31.71,35.5 31.71,25.59 31.01,24.89 v1(30.99,24.89)
  BOTTOM w0.127: U11.24 30.25,24.36 C392.2 R1218.2 29.59,26.04 30.73,24.89 v1(30.99,24.89) ; v1(31.89,40.07) 32.07,40.07 32.76,40.76 32.76,41.52 33.39,42.15 33.82,42.15 34.8,43.14 v1(34.8,43.81) ; v1(34.11,53.09) 34.11,48.97 v1(32.38,47.24)
LED1/PHYAD1: length 49.5
  TOP w0.127: v1(20.4,43.71) 20.68,43.71 21.44,42.95 21.44,41.43 22.59,40.28 22.59,37.04 21.93,36.39 21.93,31.55 21.57,31.19 21.57,28.89 21.15,28.47 21.15,27.61 v1(21.49,27.27) ; J12.11 19.73,56.18 18.14,54.58 v1(17.42,54.58)
  BOTTOM w0.127: v1(20.4,43.71) 17.68,43.71 17.25,44.15 17.24,44.15 16.08,45.31 16.08,53.24 v1(17.42,54.58) ; v1(21.49,27.27) 21.65,27.11 R1217.2 C393.1 29.27,26.54 29.84,26.54 30.1,26.29 30.1,26.08 30.82,25.36 32.41,25.36 32.54,25.23 U11.25
MIC_IN1: length 5.3
  TOP w0.203: v1(92.61,67.59) 92.68,67.52 C365.1 93.03,67.23 J34.1
  BOTTOM w0.203: v1(92.61,67.59) 93.35,67.59 D40.1 93.88,66.39 93.91,66.36 R169.1
MIC_IN2: length 7.1
  TOP w0.203: D41.1 91.56,51 91.62,50.95 R167.1 ; D41.1 90.16,51 90.16,51 C366.1 ; D41.1 90.58,51.28 90.29,51.57 J45.1 90.29,53.58 v1(89.56,54.31)
  BOTTOM w0.203: TP3.1 90,54.69 89.95,54.69 v1(89.56,54.31)
MIC_L_IN: length 51.4
  TOP w0.203: C366.2 89.14,50.44 89.1,50.44 88.49,51.06 88.49,60.23 88.25,60.46 88.25,63.52 v1(88.01,63.76) ; v1(86.44,65.61) 86.4,65.66 85.88,65.66 84.96,64.74 69.12,64.74 67.42,63.05 67.42,54.49 66.96,54.03 64.87,54.03 63.03,52.19 M1.10
  BOTTOM w0.203: v1(88.01,63.76) 88.01,64.05 v1(86.44,65.61)
MIC_R_IN: length 41.7
  TOP w0.203: M1.11 62.03,51.8 63.07,52.83 63.07,52.83 64.59,54.36 66.83,54.36 67.09,54.62 67.09,63.18 68.98,65.07 84.82,65.07 86.04,66.29 88.39,66.29 88.99,65.69 90.31,65.69 91.49,66.88 C365.2
MIPI_CSI_RX_CLK0N: length 33.1
  TOP w0.102: M1.105 43.03,12.12 43.31,12.4 43.31,15.71 44.5,17.14 45.7,17.91 47.39,18.41 54.78,18.41 55.77,18.14 59.43,15.97 60.25,15.01 60.25,13.39 60.34,13.3 60.7,13.3 v1(60.81,13.41)
  BOTTOM w0.102: v1(60.81,13.41) 60.6,13.21 60.35,13.21 60.07,12.93 60.07,12.45 60.79,11.72 60.79,7.56 60.67,7.44 J10.17
MIPI_CSI_RX_CLK0P: length 33.1
  TOP w0.102: M1.106 44.03,12.13 43.56,12.6 43.56,15.62 44.67,16.95 45.81,17.67 47.43,18.16 54.75,18.16 55.67,17.91 59.26,15.78 59.99,14.92 59.99,14.42 59.89,14.31 59.66,14.31 59.56,14.21 59.56,14.01 59.66,13.91 59.89,13.91 59.99,13.81 59.99,13.28 60.23,13.05 60.51,13.05 60.81,12.75 v1(60.81,12.73)
  BOTTOM w0.102: J10.18 61.17,7.44 61.05,7.56 61.05,11.83 60.33,12.55 60.33,12.83 60.45,12.95 60.71,12.95 60.81,12.85 v1(60.81,12.73)
MIPI_CSI_RX_D0N: length 30.9
  TOP w0.102: v1(52.79,13.46) 52.66,13.34 52.2,13.34 51.41,12.54 51.41,12.29 51.03,11.92 M1.113
  BOTTOM w0.102: J10.11 57.67,7.25 57.79,7.37 57.79,7.96 58.01,8.17 58.22,8.17 58.6,8.55 58.6,8.99 58.85,9.24 59.21,9.24 59.31,9.34 59.31,9.75 59.21,9.85 58.92,9.85 58.67,10.1 58.67,10.67 58.04,11.3 57.76,11.3 57.66,11.2 57.66,10.41 57.41,10.16 56.92,10.16 56.67,10.41 56.67,11.2 56.57,11.3 55.86,11.3 55.75,11.19 55.75,10.67 55.5,10.41 54.99,10.41 54.74,10.67 54.74,12.7 54.61,12.83 54.21,12.83 54.1,12.72 54.1,10.29 53.85,10.03 53.34,10.03 53.09,10.29 53.09,11.81 52.96,11.94 52.6,11.94 52.45,11.79 52.45,10.67 52.2,10.41 51.69,10.41 51.44,10.67 51.44,11.68 50.78,12.34 50.78,12.71 51.02,12.95 51.84,12.95 52.22,13.34 52.66,13.34 v1(52.79,13.46)
MIPI_CSI_RX_D0P: length 30.9
  TOP w0.102: v1(52.79,12.78) 52.79,12.81 52.51,13.08 52.3,13.08 52.19,12.96 52.19,12.83 52.25,12.77 52.25,12.64 52.15,12.54 52,12.54 51.96,12.58 51.81,12.58 51.66,12.44 51.66,12.35 52.03,11.98 M1.114
  BOTTOM w0.102: J10.12 58.17,7.24 58.05,7.36 58.05,7.85 58.11,7.92 58.33,7.92 58.85,8.44 58.85,8.88 58.95,8.98 59.31,8.98 59.56,9.23 59.56,9.85 59.31,10.1 59.03,10.1 58.93,10.2 58.93,10.77 58.14,11.56 57.65,11.56 57.4,11.31 57.4,10.52 57.3,10.41 57.02,10.41 56.92,10.52 56.92,11.31 56.67,11.56 55.76,11.56 55.5,11.3 55.5,10.77 55.39,10.67 55.1,10.67 54.99,10.77 54.99,12.81 54.72,13.08 54.1,13.08 53.85,12.83 53.85,10.39 53.74,10.29 53.45,10.29 53.34,10.39 53.34,11.92 53.06,12.19 52.5,12.19 52.2,11.89 52.2,10.77 52.09,10.67 51.79,10.67 51.69,10.77 51.69,11.79 51.04,12.44 51.04,12.61 51.13,12.7 51.69,12.7 51.89,12.5 52.04,12.5 52.17,12.62 52.17,12.74 52.13,12.79 52.13,12.88 52.32,13.08 52.54,13.08 52.79,12.83 v1(52.79,12.78)
MIPI_CSI_RX_D1N: length 31
  TOP w0.102: v1(50.55,14.44) 50.75,14.24 50.75,13.92 50.61,13.78 50.61,13.43 50.88,13.16 50.88,13.02 50.6,12.73 50.45,12.73 50.18,13 49.83,13 49.41,12.58 49.41,12.32 49.03,11.95 M1.111
  BOTTOM w0.102: v1(50.55,14.44) 50.77,14.21 50.77,13.66 50.97,13.46 51.69,13.46 52.07,13.84 52.07,15.01 52.18,15.11 52.45,15.11 52.58,14.99 52.58,14.24 52.83,13.99 53.22,13.99 53.47,14.24 53.47,14.99 53.59,15.11 53.85,15.11 53.98,14.99 53.98,13.97 54.23,13.72 54.74,13.72 54.99,13.97 54.99,14.99 55.12,15.11 55.37,15.11 55.5,14.99 55.5,14.19 55.75,13.94 56.43,13.94 56.61,13.76 56.61,13.51 56.43,13.33 55.75,13.33 55.5,13.08 55.5,12.34 55.77,12.06 58.29,12.06 58.71,11.65 59.07,11.65 59.4,11.98 59.54,11.98 59.83,11.69 59.83,11.55 59.5,11.21 59.5,10.86 60.07,10.29 60.07,8.69 59.29,7.91 59.29,7.35 59.17,7.23 J10.14
MIPI_CSI_RX_D1P: length 31
  TOP w0.102: M1.112 50.03,11.94 49.66,12.32 49.66,12.47 49.93,12.75 50.08,12.75 50.35,12.48 50.7,12.48 51.14,12.91 51.14,13.27 50.87,13.54 50.87,13.68 51,13.81 51,14.21 v1(51.23,14.44)
  BOTTOM w0.102: v1(51.23,14.44) 51.03,14.24 51.03,13.77 51.08,13.72 51.58,13.72 51.82,13.95 51.82,15.11 52.07,15.37 52.56,15.37 52.83,15.09 52.83,14.34 52.93,14.24 53.11,14.24 53.21,14.34 53.21,15.09 53.49,15.37 53.95,15.37 54.23,15.09 54.23,14.07 54.33,13.97 54.63,13.97 54.74,14.08 54.74,15.09 55.01,15.37 55.48,15.37 55.75,15.09 55.75,14.3 55.85,14.19 56.53,14.19 56.86,13.87 56.86,13.4 56.53,13.08 55.85,13.08 55.75,12.97 55.75,12.45 55.88,12.32 58.4,12.32 58.82,11.9 58.96,11.9 59.29,12.23 59.65,12.23 60.09,11.8 60.09,11.44 59.75,11.11 59.75,10.97 60.33,10.39 60.33,8.59 59.55,7.81 59.55,7.38 59.67,7.26 J10.15
MIPI_CSI_RX_D2N: length 32
  TOP w0.102: M1.109 47.03,12.11 47.41,12.48 47.41,12.79 47.12,13.08 47.12,16.36 47.65,16.89 53.45,16.89 54.15,16.18 54.15,13.82 54.49,13.48 57.92,13.48 58.17,13.23 58.17,12.97 v1(58.37,12.77)
  BOTTOM w0.102: v1(58.37,12.77) 58.17,12.97 58.17,13.21 59.31,14.35 60.6,14.35 62.43,12.52 62.43,9.2 61.98,8.74 61.98,8.15 62.29,7.83 62.29,7.3 62.17,7.18 J10.20
MIPI_CSI_RX_D2P: length 32.1
  TOP w0.102: v1(57.68,12.77) 57.91,13 57.91,13.13 57.82,13.22 54.39,13.22 53.9,13.71 53.9,16.08 53.34,16.64 47.75,16.64 47.37,16.26 47.37,13.19 47.66,12.9 47.66,12.54 48.03,12.17 M1.110
  BOTTOM w0.102: J10.21 62.67,7.18 62.55,7.3 62.55,7.94 62.23,8.26 62.23,8.64 62.69,9.09 62.69,12.62 60.71,14.61 59.2,14.61 57.91,13.31 57.91,13 v1(57.68,12.77)
MIPI_CSI_RX_D3N: length 33.1
  TOP w0.102: v1(57.33,14.66) 57.1,14.89 57.1,15.27 54.72,17.65 47.39,17.65 46.1,16.36 46.1,14.84 45.75,14.48 45.75,13.69 45.97,13.46 46.05,13.46 46.15,13.36 46.15,12.96 46.05,12.86 45.65,12.86 45.41,12.62 45.41,12.39 45.03,12.01 M1.107
  BOTTOM w0.102: J10.23 63.67,7.44 63.79,7.56 63.79,12.17 60.85,15.11 57.18,15.11 57.1,15.04 57.1,14.89 v1(57.33,14.66)
MIPI_CSI_RX_D3P: length 33
  TOP w0.102: v1(56.64,14.66) 56.85,14.86 56.85,15.16 54.61,17.4 47.5,17.4 46.35,16.26 46.35,14.73 46,14.38 46,13.8 46.08,13.72 46.16,13.72 46.41,13.47 46.41,12.86 46.16,12.61 45.76,12.61 45.66,12.51 45.66,12.38 46.03,12.01 M1.108
  BOTTOM w0.102: J10.24 64.17,7.44 64.05,7.56 64.05,12.28 60.96,15.37 57.07,15.37 56.85,15.14 56.85,14.86 v1(56.64,14.66)
MIPI_DSI_TX0_CLKN/LVDS_TX0_CLKN: length 30.1
  TOP w0.102: J7.17 84.05,6.17 83.92,6.05 83.92,5.81 83.59,5.48 83.59,4.4 81.48,2.29 69.8,2.29 69.16,2.93 69.16,6.62 67.4,8.38 67.39,8.38 67.38,8.39 67.38,8.4 66,9.78 64.54,9.78 63.41,10.91 63.41,11.19 M1.125
MIPI_DSI_TX0_CLKP/LVDS_TX0_CLKP: length 30
  TOP w0.102: J7.18 83.55,6.14 83.67,6.02 83.67,5.92 83.34,5.59 83.34,4.5 81.38,2.54 69.91,2.54 69.42,3.03 69.42,6.72 66.11,10.03 64.64,10.03 64.45,10.23 64.45,10.37 64.69,10.61 64.69,10.75 64.54,10.89 64.4,10.89 64.16,10.66 64.02,10.66 63.66,11.02 63.66,11.19 M1.126
MIPI_DSI_TX0_D0N/LVDS_TX0_D0N: length 27.7
  TOP w0.102: v1(78.16,11.94) 77.95,11.73 77.95,11.61 78.08,11.49 78.39,11.49 79.35,12.45 79.76,12.45 80.52,11.68 80.52,9.37 80.62,9.27 85.87,9.27 85.97,9.37 85.97,10.09 86.22,10.34 86.84,10.34 87.09,10.09 87.09,9.37 87.19,9.27 87.99,9.27 88.42,8.84 88.42,7.56 88.55,7.44 J7.8 ; v1(73.86,10.91) 73.67,11.1 73.05,11.1 72.58,10.63 71.74,10.63 71.41,10.96 71.41,11.19 M1.133
  BOTTOM w0.102: v1(78.16,11.94) 77.95,11.73 77.95,11.37 77.7,11.12 76.73,11.12 76.48,11.37 76.48,11.71 76.37,11.81 75.97,11.81 75.87,11.71 75.87,11.37 75.62,11.12 74.07,11.12 v1(73.86,10.91)
MIPI_DSI_TX0_D0P/LVDS_TX0_D0P: length 27.7
  TOP w0.102: J7.9 88.05,7.44 88.17,7.56 88.17,7.89 88.07,8 87.73,8 87.63,8.1 87.63,8.3 87.73,8.4 88.07,8.4 88.17,8.5 88.17,8.73 87.88,9.02 87.08,9.02 86.83,9.27 86.83,9.98 86.73,10.08 86.33,10.08 86.22,9.98 86.22,9.27 85.97,9.02 80.51,9.02 80.26,9.27 80.26,11.58 79.65,12.19 79.45,12.19 78.49,11.23 77.98,11.23 77.7,11.51 77.7,11.73 v1(77.49,11.94) ; v1(73.86,11.59) 73.62,11.35 72.95,11.35 72.48,10.88 71.84,10.88 71.66,11.07 71.66,11.19 M1.134
  BOTTOM w0.102: v1(73.86,11.59) 74.07,11.37 75.51,11.37 75.61,11.48 75.61,11.81 75.86,12.06 76.48,12.06 76.73,11.81 76.73,11.48 76.83,11.37 77.6,11.37 77.7,11.48 77.7,11.73 v1(77.49,11.94)
MIPI_DSI_TX0_D1N/LVDS_TX0_D1N: length 27.6
  TOP w0.102: v1(72.16,9.44) 71.94,9.65 70.72,9.65 69.41,10.96 69.41,11.19 M1.131 ; J7.11 87.05,7.44 86.92,7.56 86.92,7.95 86.36,8.51 78.61,8.51 78.51,8.61 78.51,8.79 79.76,10.03 79.76,10.41 79.25,10.92 78.89,10.92 77.7,9.73 77.05,9.73 76.91,9.88 76.91,10.31 v1(77.1,10.5)
  BOTTOM w0.102: v1(72.16,9.44) 72.37,9.65 73.28,9.65 73.53,9.4 74.13,9.4 74.38,9.65 74.38,10.19 74.48,10.29 74.89,10.29 74.99,10.19 74.99,9.9 75.24,9.65 76.63,9.65 76.88,9.9 76.88,10.29 v1(77.1,10.5)
MIPI_DSI_TX0_D1P/LVDS_TX0_D1P: length 27.6
  TOP w0.102: v1(76.42,10.5) 76.65,10.27 76.65,9.78 76.95,9.48 77.8,9.48 78.99,10.67 79.14,10.67 79.5,10.31 79.5,10.14 78.26,8.89 78.26,8.51 78.51,8.26 86.25,8.26 86.67,7.84 86.67,7.56 86.55,7.44 J7.12 ; v1(72.16,10.12) 71.94,9.91 70.82,9.91 70.46,10.26 70.46,10.41 70.7,10.64 70.7,10.79 70.55,10.93 70.41,10.93 70.18,10.69 70.03,10.69 69.66,11.07 69.66,11.19 M1.132
  BOTTOM w0.102: v1(76.42,10.5) 76.63,10.29 76.63,10.01 76.53,9.91 75.35,9.91 75.24,10.01 75.24,10.29 74.99,10.54 74.38,10.54 74.13,10.29 74.13,9.75 74.02,9.65 73.64,9.65 73.38,9.91 72.37,9.91 v1(72.16,10.12)
MIPI_DSI_TX0_D2N/LVDS_TX0_D2N: length 28.3
  TOP w0.102: J7.14 85.55,7.16 85.42,7.29 85.42,7.5 85.17,7.75 77.32,7.75 76.45,8.61 76.45,8.81 v1(76.67,9.02) ; v1(73.29,8.04) 73.08,8.26 72.52,8.26 72.14,8.64 71.73,8.64 71.63,8.53 71.63,8.23 72.14,7.73 72.14,7.15 71.76,6.77 71.21,6.77 69.93,8.05 69.93,8.4 70.25,8.73 70.25,8.87 69.96,9.16 69.82,9.16 69.5,8.83 69.14,8.83 68.71,9.27 68.71,9.62 69.03,9.95 69.03,10.09 68.72,10.41 68.57,10.41 68.25,10.08 67.89,10.08 67.41,10.57 67.41,11.19 M1.129
  BOTTOM w0.102: v1(73.29,8.04) 73.5,8.26 76.2,8.26 76.45,8.51 76.45,8.81 v1(76.67,9.02)
MIPI_DSI_TX0_D2P/LVDS_TX0_D2P: length 28.3
  TOP w0.102: v1(75.99,9.02) 76.2,8.81 76.2,8.51 76.36,8.35 76.36,8.2 76.12,7.97 76.12,7.82 76.27,7.68 76.41,7.68 76.65,7.92 76.79,7.92 77.22,7.49 85.07,7.49 85.17,7.39 85.17,7.32 85.05,7.2 J7.15 ; v1(73.29,8.72) 73.08,8.51 72.62,8.51 72.24,8.89 71.62,8.89 71.37,8.64 71.37,8.13 71.88,7.62 71.88,7.26 71.65,7.03 71.31,7.03 70.18,8.15 70.18,8.3 70.51,8.62 70.51,8.97 70.07,9.41 69.72,9.41 69.39,9.09 69.25,9.09 68.96,9.38 68.96,9.52 69.28,9.84 69.28,10.2 68.82,10.66 68.47,10.66 68.14,10.34 68,10.34 67.66,10.68 67.66,11.19 M1.130
  BOTTOM w0.102: v1(73.29,8.72) 73.5,8.51 76.09,8.51 76.2,8.61 76.2,8.81 v1(75.99,9.02)
MIPI_DSI_TX0_D3N/LVDS_TX0_D3N: length 28.9
  TOP w0.102: J7.20 82.55,5.87 82.38,5.71 82.38,4.41 81.92,3.94 79.27,3.94 79.17,3.84 79.17,3.3 78.92,3.05 78.3,3.05 78.05,3.3 78.05,3.84 77.95,3.94 76.43,3.94 76.33,3.84 76.33,3.45 76.05,3.17 75.46,3.17 75.18,3.45 75.18,5.1 75.08,5.21 74.52,5.21 74.42,5.11 74.42,4.19 74.17,3.94 72.44,3.94 71.93,4.44 71.93,5.92 71.75,6.1 70.76,6.1 66.32,10.54 65.68,10.54 65.41,10.82 65.41,11.19 M1.127
MIPI_DSI_TX0_D3P/LVDS_TX0_D3P: length 28.8
  TOP w0.102: J7.21 82.05,5.87 82.13,5.79 82.13,5.42 82.03,5.32 81.71,5.32 81.61,5.22 81.61,5.02 81.71,4.91 82.03,4.91 82.13,4.81 82.13,4.51 81.81,4.19 79.16,4.19 78.91,3.94 78.91,3.4 78.81,3.3 78.41,3.3 78.3,3.4 78.3,3.94 78.05,4.19 76.32,4.19 76.07,3.94 76.07,3.56 75.95,3.43 75.56,3.43 75.44,3.56 75.44,5.21 75.18,5.46 74.42,5.46 74.17,5.21 74.17,4.29 74.07,4.19 72.54,4.19 72.19,4.55 72.19,6.02 71.86,6.35 70.87,6.35 66.42,10.79 65.79,10.79 65.66,10.92 65.66,11.19 M1.128
MIPI_DSI_TX1_CLKN: length 33.3
  TOP w0.102: M1.115 53.41,11.19 53.41,10.97 53.29,10.85 39.25,10.85 38.69,10.29 36.71,10.29 36.46,10.04 36.46,9.25 36.35,9.14 35.95,9.14 35.85,9.25 35.85,10.04 35.6,10.29 34.95,10.29 34.67,10.01 34.67,9.72 34.57,9.62 33.91,9.62 33.66,9.37 33.66,8.75 33.91,8.5 34.57,8.5 34.67,8.4 34.67,8.34 34.99,8.03 36.83,8.03 37.36,7.49 41.68,7.49 41.7,7.47 41.7,7.31 41.58,7.19 J8.27
MIPI_DSI_TX1_CLKP: length 33.3
  TOP w0.102: M1.116 53.66,11.19 53.66,10.86 53.39,10.59 39.35,10.59 38.79,10.03 36.81,10.03 36.71,9.93 36.71,9.14 36.46,8.89 35.84,8.89 35.59,9.14 35.59,9.93 35.49,10.03 35.05,10.03 34.92,9.91 34.92,9.62 34.67,9.37 34.01,9.37 33.91,9.27 33.91,8.86 34.01,8.76 34.67,8.76 34.92,8.51 34.92,8.45 35.09,8.28 36.93,8.28 37.47,7.75 41.78,7.75 41.96,7.57 41.96,7.29 42.08,7.17 J8.26
MIPI_DSI_TX1_D0N: length 35.6
  TOP w0.102: J8.33 38.58,5.87 38.7,5.75 38.7,5.01 39.31,4.4 42.21,1.5 57.76,1.5 58.55,2.29 58.55,3.22 58.72,3.4 58.92,3.4 v1(59.12,3.19) ; v1(58.07,4.48) 58.29,4.69 58.29,6.45 59.31,7.47 59.31,8.13 61.41,10.22 61.41,11.19 M1.123
  BOTTOM w0.102: v1(59.12,3.19) 58.92,3.39 58.53,3.39 58.28,3.64 58.28,4.26 v1(58.07,4.48)
MIPI_DSI_TX1_D0P: length 35.6
  TOP w0.102: J8.32 39.08,5.87 38.96,5.75 38.96,5.11 39.13,4.94 39.27,4.94 39.53,5.19 39.64,5.19 39.8,5.03 39.8,4.9 39.56,4.65 39.56,4.51 42.32,1.75 57.65,1.75 58.29,2.39 58.29,3.32 58.62,3.65 58.9,3.65 v1(59.12,3.87) ; M1.124 61.66,11.19 61.66,10.12 59.56,8.02 59.56,7.37 58.54,6.34 58.54,4.68 v1(58.74,4.48)
  BOTTOM w0.102: v1(58.74,4.48) 58.53,4.26 58.53,3.74 58.63,3.64 58.89,3.64 v1(59.12,3.87)
MIPI_DSI_TX1_D1N: length 34.4
  TOP w0.102: v1(56.72,8.9) 56.93,8.69 57.23,8.69 57.78,8.13 57.78,6.5 57.61,6.33 57.61,2.58 57.32,2.29 42.55,2.29 41.55,3.28 41.55,3.59 41.91,3.94 41.91,4.09 41.6,4.39 41.46,4.39 41.13,4.06 40.77,4.06 40.2,4.63 40.2,5.75 40.08,5.87 J8.30 ; v1(58,9.99) 58.21,9.78 59.08,9.78 59.41,10.11 59.41,11.19 M1.121
  BOTTOM w0.102: v1(58,9.99) 57.79,9.78 57.53,9.78 57.28,9.52 57.28,8.79 57.18,8.69 56.93,8.69 v1(56.72,8.9)
MIPI_DSI_TX1_D1P: length 34.5
  TOP w0.102: M1.122 59.66,11.19 59.66,10 59.18,9.53 58.21,9.53 v1(58,9.31) ; v1(56.72,8.22) 56.93,8.43 57.12,8.43 57.53,8.02 57.53,6.6 57.36,6.43 57.36,2.68 57.22,2.54 42.65,2.54 41.81,3.38 41.81,3.48 42.16,3.84 42.16,4.19 41.71,4.65 41.35,4.65 41.02,4.32 40.87,4.32 40.46,4.73 40.46,4.99 40.56,5.1 40.92,5.1 41.02,5.2 41.02,5.4 40.92,5.5 40.56,5.5 40.46,5.6 40.46,5.75 40.58,5.87 J8.29
  BOTTOM w0.102: v1(56.72,8.22) 56.93,8.43 57.28,8.43 57.53,8.68 57.53,9.42 57.64,9.53 57.79,9.53 v1(58,9.31)
MIPI_DSI_TX1_D2N: length 33.2
  TOP w0.102: M1.119 57.41,11.19 57.41,10.65 56.54,9.78 56.14,9.78 v1(55.94,9.99) ; J8.24 43.08,6.14 43.2,6.02 43.2,4.95 43.87,4.28 44.23,4.28 44.61,4.67 44.76,4.67 45.04,4.38 45.04,4.24 44.66,3.85 44.66,3.5 45.03,3.13 47.31,3.13 47.56,3.38 47.56,4.6 47.66,4.7 48.07,4.7 48.17,4.6 48.17,3.38 48.42,3.13 50.1,3.13 50.42,3.45 50.42,4.09 50.52,4.19 50.87,4.19 50.97,4.09 50.97,3.43 51.22,3.17 51.84,3.17 52.09,3.43 52.09,4.09 52.19,4.19 52.6,4.19 52.7,4.09 52.7,3.43 52.95,3.17 53.57,3.17 53.82,3.43 53.82,4.09 53.92,4.19 54.36,4.19 55.17,5 55.17,5.84 55.69,6.36 55.69,7.79 55.37,8.11 55.37,9.6 55.14,9.83 54.82,9.83 v1(54.66,9.99)
  BOTTOM w0.102: v1(54.66,9.99) 54.88,9.78 55.72,9.78 v1(55.94,9.99)
MIPI_DSI_TX1_D2P: length 33.2
  TOP w0.102: v1(54.66,9.31) 54.66,9.39 54.85,9.58 55.03,9.58 55.12,9.49 55.12,8.86 55.02,8.76 54.74,8.76 54.64,8.66 54.64,8.45 54.74,8.35 55.02,8.35 55.12,8.25 55.12,8 55.43,7.69 55.43,6.47 54.91,5.95 54.91,5.11 54.25,4.45 53.82,4.45 53.57,4.19 53.57,3.53 53.46,3.43 53.06,3.43 52.96,3.53 52.96,4.19 52.71,4.45 52.09,4.45 51.84,4.19 51.84,3.53 51.74,3.43 51.33,3.43 51.23,3.53 51.23,4.19 50.98,4.45 50.42,4.45 50.16,4.19 50.16,3.56 49.99,3.38 48.53,3.38 48.43,3.48 48.43,4.7 48.18,4.95 47.56,4.95 47.31,4.7 47.31,3.48 47.21,3.38 45.13,3.38 44.91,3.6 44.91,3.75 45.3,4.13 45.3,4.49 44.86,4.92 44.51,4.92 44.12,4.54 43.98,4.54 43.46,5.06 43.46,6.04 43.58,6.17 J8.23 ; v1(55.94,9.31) 56.15,9.53 56.65,9.53 57.66,10.54 57.66,11.19 M1.120
  BOTTOM w0.102: v1(55.94,9.31) 55.94,9.34 55.75,9.53 54.88,9.53 v1(54.66,9.31)
MIPI_DSI_TX1_D3N: length 35.1
  TOP w0.102: M1.117 55.41,11.19 55.41,10.93 55.27,10.79 54.38,10.79 53.67,10.08 53.26,10.08 52.93,9.75 52.93,8.48 52.83,8.38 52.42,8.38 52.32,8.48 52.32,9.78 52.02,10.08 45.23,10.08 44.98,9.83 44.98,9.75 44.88,9.65 44.47,9.65 44.37,9.75 44.37,9.83 44.12,10.08 43.57,10.08 43.32,9.83 43.32,9.37 43.22,9.27 42.81,9.27 42.71,9.37 42.71,9.83 42.46,10.08 41.7,10.08 41.45,9.83 41.45,9.37 41.35,9.27 40.94,9.27 40.84,9.37 40.84,9.83 40.59,10.08 39.93,10.08 39.37,9.53 37.47,9.53 37.21,9.27 37.21,8.51 37.47,8.26 44.07,8.26 44.7,7.62 44.7,7.37 44.58,7.24 J8.21
MIPI_DSI_TX1_D3P: length 35.1
  TOP w0.102: J8.20 45.08,7.24 44.96,7.37 44.96,7.73 44.17,8.51 37.57,8.51 37.47,8.61 37.47,9.17 37.57,9.27 39.48,9.27 40.03,9.83 40.48,9.83 40.59,9.73 40.59,9.27 40.84,9.02 41.45,9.02 41.7,9.27 41.7,9.73 41.81,9.83 42.36,9.83 42.46,9.73 42.46,9.27 42.71,9.02 43.33,9.02 43.58,9.27 43.58,9.73 43.68,9.83 44.01,9.83 44.12,9.73 44.12,9.65 44.37,9.4 44.98,9.4 45.23,9.65 45.23,9.73 45.34,9.83 51.91,9.83 52.06,9.68 52.06,8.38 52.31,8.13 52.93,8.13 53.18,8.38 53.18,9.64 53.37,9.83 53.77,9.83 54.48,10.54 55.37,10.54 55.66,10.83 55.66,11.19 M1.118
MIPI_DSI_TX1_RST: length 3.7
  TOP w0.127: J8.36 37.08,7.21 36.7,7.59 34.64,7.59 R342.2
PHY_INT: length 1.8
  BOTTOM w0.127: R1219.1 34.8,19.7 35.04,19.94 U11.11
